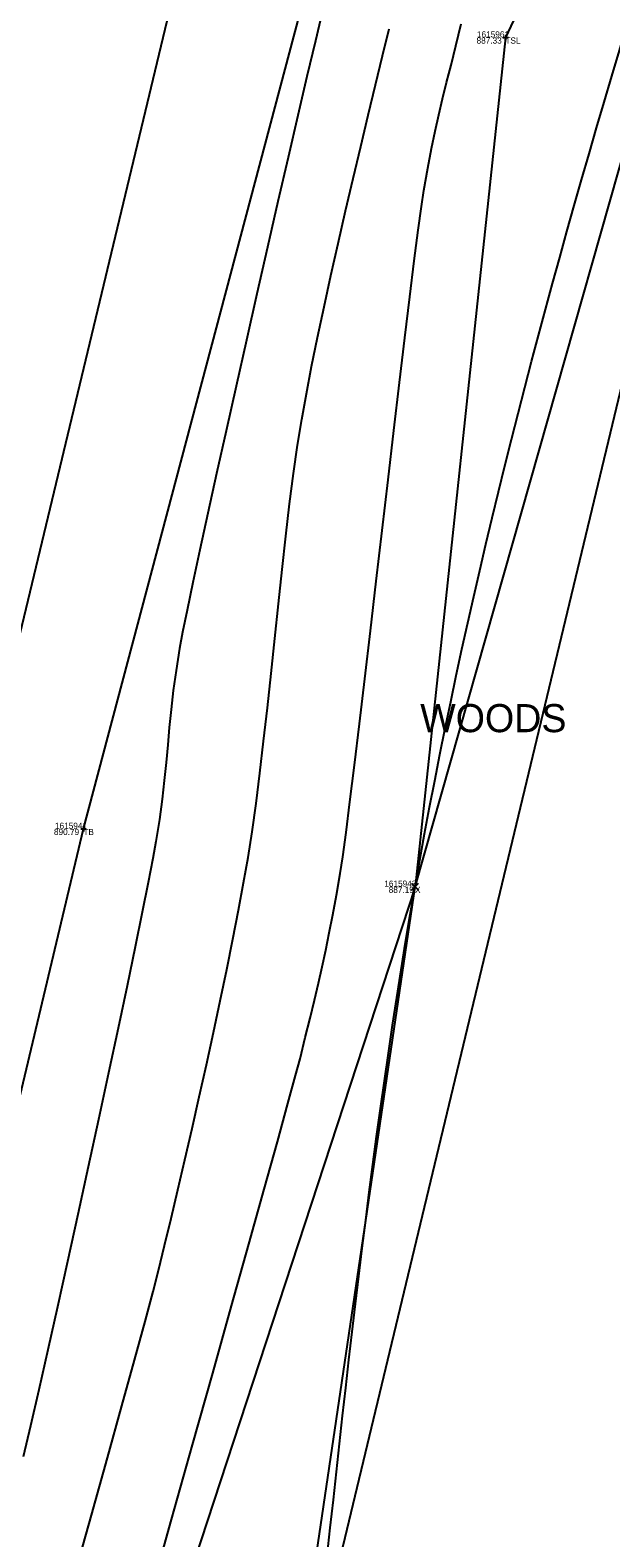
# Model space of a CAD drawing. Extents: x 1957117 to 1971063, y 701601 to 715861.
# Drawn here: x 1963126.8 to 1963159.8, y 705169.7 to 705255.5 of the extents above; entities that cross this region are included whole.
import ezdxf

# ---------------------------------------------------------------- set-up
doc = ezdxf.new("R2010")
doc.units = 0
for name, color, linetype in [('AP_X_Lights', 7, 'Continuous'), ('DT_X_Break_Line', 7, 'Continuous'), ('DT_X_Contour_Major', 7, 'Continuous'), ('DT_X_Contour_Minor', 7, 'Continuous'), ('DT_X_TIN_Hull', 7, 'Continuous'), ('GE_X_CL_20', 7, 'Continuous'), ('HY_X_Water_Edge', 7, 'Continuous'), ('PV_P_Drive', 7, 'Continuous'), ('PV_P_Shoulder', 7, 'Continuous'), ('RS_Raster1', 7, 'Continuous'), ('RW_X_Esmt_RR', 7, 'Continuous'), ('SC_Scratch1', 7, 'Continuous'), ('SC_Shading5', 7, 'Continuous'), ('VG_X_Text', 7, 'Continuous')]:
    doc.layers.add(name, color=color, linetype=linetype)

msp = doc.modelspace()

# ---------------------------------------------------------------- linework, layer by layer
at = {"layer": 'AP_X_Lights'}
for p, q in [((1963148.491, 705206.545), (1963148.879, 705206.935)), ((1963148.491, 705206.935), (1963148.879, 705206.545))]:
    msp.add_line(p, q, dxfattribs=at)
at = {"layer": 'DT_X_Break_Line'}
for points in [[(1963097.69, 705062.728), (1963110.134, 705110.941), (1963118.179, 705161.08), (1963129.819, 705210.034), (1963142.677, 705258.498), (1963154.883, 705308.22), (1963169.696, 705358.61), (1963178.568, 705401.323), (1963191.579, 705451.786), (1963203.047, 705496.926), (1963213.073, 705549.098), (1963225.99, 705592.54), (1963238.509, 705645.64), (1963250.08, 705699.351), (1963260.722, 705745.719)], [(1963274.602, 705735.973), (1963275.289, 705693.429), (1963252.817, 705638.247), (1963242.54, 705592.994), (1963230.124, 705549.475), (1963219.532, 705497.27), (1963210.988, 705447.286), (1963195.628, 705399.31), (1963191.635, 705353.417), (1963175.48, 705301.059), (1963153.825, 705255.066), (1963148.685, 705206.74), (1963116.889, 705109.729), (1963101.597, 705034.688)]]:
    msp.add_lwpolyline(points, dxfattribs=at)
at = {"layer": 'DT_X_Contour_Major'}
msp.add_lwpolyline([(1963143.438, 705256.654), (1963143.014, 705254.873), (1963142.538, 705252.851), (1963142.019, 705250.626), (1963141.465, 705248.237), (1963140.887, 705245.724), (1963140.292, 705243.128), (1963139.69, 705240.486), (1963139.091, 705237.839), (1963138.503, 705235.227), (1963137.935, 705232.688), (1963137.396, 705230.263), (1963136.896, 705227.99), (1963136.444, 705225.91), (1963136.048, 705224.061), (1963135.719, 705222.484), (1963135.464, 705221.218), (1963135.293, 705220.302), (1963135.091, 705219.051), (1963134.933, 705217.902), (1963134.808, 705216.829), (1963134.705, 705215.806), (1963134.614, 705214.809), (1963134.523, 705213.811), (1963134.421, 705212.789), (1963134.299, 705211.715), (1963134.144, 705210.565), (1963133.947, 705209.313), (1963133.77, 705208.337), (1963133.507, 705206.981), (1963133.167, 705205.293), (1963132.762, 705203.319), (1963132.3, 705201.106), (1963131.792, 705198.7), (1963131.248, 705196.148), (1963130.678, 705193.496), (1963130.092, 705190.792), (1963129.5, 705188.082), (1963128.913, 705185.411), (1963128.34, 705182.828), (1963127.792, 705180.379), (1963127.278, 705178.11), (1963126.808, 705176.068), (1963126.393, 705174.299)], dxfattribs=at)
msp.add_lwpolyline([(1963143.438, 705256.654), (1963143.014, 705254.873), (1963142.538, 705252.851), (1963142.019, 705250.626), (1963141.465, 705248.237), (1963140.887, 705245.724), (1963140.292, 705243.128), (1963139.69, 705240.486), (1963139.091, 705237.839), (1963138.503, 705235.227), (1963137.935, 705232.688), (1963137.396, 705230.263), (1963136.896, 705227.99), (1963136.444, 705225.91), (1963136.048, 705224.061), (1963135.719, 705222.484), (1963135.464, 705221.218), (1963135.293, 705220.302), (1963135.091, 705219.051), (1963134.933, 705217.902), (1963134.808, 705216.829), (1963134.705, 705215.806), (1963134.614, 705214.809), (1963134.523, 705213.811), (1963134.421, 705212.789), (1963134.299, 705211.715), (1963134.144, 705210.565), (1963133.947, 705209.313), (1963133.77, 705208.337), (1963133.507, 705206.981), (1963133.167, 705205.293), (1963132.762, 705203.319), (1963132.3, 705201.106), (1963131.792, 705198.7), (1963131.248, 705196.148), (1963130.678, 705193.496), (1963130.092, 705190.792), (1963129.5, 705188.082), (1963128.913, 705185.411), (1963128.34, 705182.828), (1963127.792, 705180.379), (1963127.278, 705178.11), (1963126.808, 705176.068), (1963126.393, 705174.299)], dxfattribs=at)
at = {"layer": 'DT_X_Contour_Minor'}
for points in [[(1963133.609, 705166.375), (1963134.835, 705170.737), (1963136.029, 705174.986), (1963137.173, 705179.057), (1963138.247, 705182.882), (1963139.232, 705186.395), (1963140.108, 705189.53), (1963140.856, 705192.219), (1963141.457, 705194.396), (1963141.892, 705195.993), (1963142.141, 705196.945), (1963142.44, 705198.156), (1963142.712, 705199.259), (1963142.96, 705200.28), (1963143.189, 705201.248), (1963143.403, 705202.191), (1963143.609, 705203.135), (1963143.809, 705204.109), (1963144.009, 705205.14), (1963144.213, 705206.255), (1963144.426, 705207.484), (1963144.57, 705208.436), (1963144.758, 705209.818), (1963144.982, 705211.577), (1963145.239, 705213.658), (1963145.522, 705216.007), (1963145.827, 705218.571), (1963146.147, 705221.295), (1963146.478, 705224.125), (1963146.813, 705227.006), (1963147.149, 705229.886), (1963147.479, 705232.71), (1963147.799, 705235.423), (1963148.101, 705237.972), (1963148.383, 705240.303), (1963148.637, 705242.362), (1963148.859, 705244.094), (1963149.044, 705245.445), (1963149.185, 705246.362), (1963149.412, 705247.631), (1963149.626, 705248.742), (1963149.833, 705249.74), (1963150.04, 705250.668), (1963150.254, 705251.572), (1963150.482, 705252.497), (1963150.73, 705253.486), (1963151.006, 705254.585), (1963151.315, 705255.839)], [(1963133.609, 705166.375), (1963134.835, 705170.737), (1963136.029, 705174.986), (1963137.173, 705179.057), (1963138.247, 705182.882), (1963139.232, 705186.395), (1963140.108, 705189.53), (1963140.856, 705192.219), (1963141.457, 705194.396), (1963141.892, 705195.993), (1963142.141, 705196.945), (1963142.44, 705198.156), (1963142.712, 705199.259), (1963142.96, 705200.28), (1963143.189, 705201.248), (1963143.403, 705202.191), (1963143.609, 705203.135), (1963143.809, 705204.109), (1963144.009, 705205.14), (1963144.213, 705206.255), (1963144.426, 705207.484), (1963144.57, 705208.436), (1963144.758, 705209.818), (1963144.982, 705211.577), (1963145.239, 705213.658), (1963145.522, 705216.007), (1963145.827, 705218.571), (1963146.147, 705221.295), (1963146.478, 705224.125), (1963146.813, 705227.006), (1963147.149, 705229.886), (1963147.479, 705232.71), (1963147.799, 705235.423), (1963148.101, 705237.972), (1963148.383, 705240.303), (1963148.637, 705242.362), (1963148.859, 705244.094), (1963149.044, 705245.445), (1963149.185, 705246.362), (1963149.412, 705247.631), (1963149.626, 705248.742), (1963149.833, 705249.74), (1963150.04, 705250.668), (1963150.254, 705251.572), (1963150.482, 705252.497), (1963150.73, 705253.486), (1963151.006, 705254.585), (1963151.315, 705255.839)], [(1963129.303, 705167.462), (1963130.283, 705170.971), (1963131.192, 705174.235), (1963132.013, 705177.198), (1963132.73, 705179.802), (1963133.326, 705181.991), (1963133.786, 705183.709), (1963134.092, 705184.898), (1963134.44, 705186.321), (1963134.811, 705187.859), (1963135.198, 705189.494), (1963135.597, 705191.205), (1963136.003, 705192.975), (1963136.412, 705194.783), (1963136.819, 705196.612), (1963137.218, 705198.443), (1963137.604, 705200.256), (1963137.974, 705202.033), (1963138.322, 705203.755), (1963138.643, 705205.402), (1963138.933, 705206.956), (1963139.187, 705208.398), (1963139.416, 705209.86), (1963139.64, 705211.468), (1963139.858, 705213.199), (1963140.072, 705215.027), (1963140.284, 705216.929), (1963140.493, 705218.881), (1963140.702, 705220.857), (1963140.911, 705222.833), (1963141.122, 705224.785), (1963141.335, 705226.689), (1963141.552, 705228.52), (1963141.775, 705230.254), (1963142.003, 705231.866), (1963142.239, 705233.332), (1963142.501, 705234.78), (1963142.804, 705236.343), (1963143.142, 705238), (1963143.51, 705239.734), (1963143.902, 705241.523), (1963144.311, 705243.35), (1963144.733, 705245.195), (1963145.162, 705247.039), (1963145.592, 705248.862), (1963146.017, 705250.645), (1963146.432, 705252.37), (1963146.831, 705254.016), (1963147.208, 705255.564)], [(1963129.303, 705167.462), (1963130.283, 705170.971), (1963131.192, 705174.235), (1963132.013, 705177.198), (1963132.73, 705179.802), (1963133.326, 705181.991), (1963133.786, 705183.709), (1963134.092, 705184.898), (1963134.44, 705186.321), (1963134.811, 705187.859), (1963135.198, 705189.494), (1963135.597, 705191.205), (1963136.003, 705192.975), (1963136.412, 705194.783), (1963136.819, 705196.612), (1963137.218, 705198.443), (1963137.604, 705200.256), (1963137.974, 705202.033), (1963138.322, 705203.755), (1963138.643, 705205.402), (1963138.933, 705206.956), (1963139.187, 705208.398), (1963139.416, 705209.86), (1963139.64, 705211.468), (1963139.858, 705213.199), (1963140.072, 705215.027), (1963140.284, 705216.929), (1963140.493, 705218.881), (1963140.702, 705220.857), (1963140.911, 705222.833), (1963141.122, 705224.785), (1963141.335, 705226.689), (1963141.552, 705228.52), (1963141.775, 705230.254), (1963142.003, 705231.866), (1963142.239, 705233.332), (1963142.501, 705234.78), (1963142.804, 705236.343), (1963143.142, 705238), (1963143.51, 705239.734), (1963143.902, 705241.523), (1963144.311, 705243.35), (1963144.733, 705245.195), (1963145.162, 705247.039), (1963145.592, 705248.862), (1963146.017, 705250.645), (1963146.432, 705252.37), (1963146.831, 705254.016), (1963147.208, 705255.564)]]:
    msp.add_lwpolyline(points, dxfattribs=at)
at = {"layer": 'DT_X_TIN_Hull'}
msp.add_lwpolyline([(1963110.114, 705008.741), (1963133.773, 705105.742), (1963148.685, 705206.74), (1963175.48, 705301.059), (1963191.635, 705353.417), (1963195.628, 705399.31), (1963210.988, 705447.286), (1963219.532, 705497.27), (1963230.124, 705549.475), (1963251.052, 705591.159), (1963275.289, 705693.429), (1963292.982, 705784.032), (1963302.841, 705839.645), (1963309.732, 705887.345), (1963335.126, 705936.766)], dxfattribs=at)
at = {"layer": 'GE_X_CL_20'}
msp.add_lwpolyline([(1963418.3, 706437.397), (1962895.621, 704261.062)], dxfattribs=at)
at = {"layer": 'HY_X_Water_Edge'}
msp.add_spline([(1963191.723, 701994.048), (1963062.047, 702441.167), (1962863.491, 703169.356), (1962827.53, 703438.691), (1962823.213, 703537.412), (1962817.962, 703593.874), (1962817.97, 703697.316), (1962828.582, 703804.235), (1962836.461, 703844.734), (1962850.687, 703896.004), (1962867.251, 703938.846), (1962873.848, 703992.355), (1962884.135, 704091.371), (1962891.241, 704140.854), (1962897.382, 704180.529), (1962905.467, 704230.979), (1962943.949, 704328.022), (1962948.537, 704378.842), (1962964.114, 704426.264), (1963004.885, 704570.73), (1963042.054, 704716.522), (1963062.038, 704814.417), (1963072.171, 704860.237), (1963090.023, 704956.798), (1963107.066, 705031.783), (1963133.773, 705105.742), (1963148.685, 705206.74), (1963175.48, 705301.059), (1963191.635, 705353.417), (1963210.988, 705447.286), (1963219.532, 705497.27), (1963230.124, 705549.475), (1963251.052, 705591.159), (1963275.289, 705693.429), (1963292.982, 705784.032), (1963302.841, 705839.645), (1963335.126, 705936.766), (1963359.752, 706046.75), (1963389.133, 706177.299), (1963417.827, 706273.456), (1963475.868, 706451.902), (1963533.782, 706640.53), (1963553.86, 706696.984), (1963580.184, 706715.425), (1963609.172, 706718.73), (1963617.062, 706714.691), (1963619.447, 706694.678), (1963564.282, 706533.07), (1963531.853, 706395.229), (1963434.4, 706006.96), (1963354.09, 705679.186), (1963237.513, 705206.07), (1963167.369, 704892.962), (1963059.145, 704434.176), (1962907.914, 703908.742), (1962877.458, 703703.326), (1962898.357, 703412.121), (1962942.65, 703052.267), (1963048.963, 702674.866), (1963191.468, 702189.666), (1963245.396, 702019.832)], degree=3, dxfattribs=at)
at = {"layer": 'PV_P_Drive'}
for p, q in [((1963153.679, 705255.066), (1963153.971, 705255.066)), ((1963153.825, 705255.212), (1963153.825, 705254.92)), ((1963153.825, 705255.066), (1963153.825, 705255.066)), ((1963129.673, 705210.034), (1963129.965, 705210.034)), ((1963129.819, 705210.18), (1963129.819, 705209.888)), ((1963129.819, 705210.034), (1963129.819, 705210.034))]:
    msp.add_line(p, q, dxfattribs=at)
at = {"layer": 'RW_X_Esmt_RR'}
msp.add_line((1962924.791, 704254.057), (1963447.47, 706430.392), dxfattribs=at)
at = {"layer": 'SC_Shading5'}
for points in [[(1963026.912, 704294.121), (1963138.818, 704737.794), (1963251.679, 705213.963), (1963374.306, 705730.111), (1963454.783, 706045.593), (1963517.244, 706296.713), (1963562.763, 706479.256), (1963580.13, 706553.799), (1963589.678, 706586.994)], [(1963609.915, 706579.703), (1963587.283, 706499.153), (1963552.056, 706354.005), (1963480.911, 706069.234), (1963357.401, 705576.869), (1963272.751, 705226.931), (1963210.247, 704956.481), (1963044.97, 704288.881)]]:
    msp.add_spline(points, degree=3, dxfattribs=at)

# ---------------------------------------------------------------- texts
at = {"layer": 'PV_P_Shoulder'}
for s, p in [('887.33', (1963152.185, 705254.716)), ('890.79', (1963128.144, 705209.684)), ('887.19', (1963147.186, 705206.39))]:
    msp.add_text(s, height=0.35, dxfattribs=at).set_placement(p)
at = {"layer": 'RS_Raster1'}
for s, p in [('1615961', (1963152.207, 705255.066)), ('1615941', (1963128.204, 705210.034)), ('1615943', (1963146.938, 705206.74))]:
    msp.add_text(s, height=0.35, dxfattribs=at).set_placement(p)
at = {"layer": 'SC_Scratch1'}
for s, p in [('TSL', (1963153.825, 705254.716)), ('TB', (1963129.819, 705209.684)), ('X', (1963148.685, 705206.39))]:
    msp.add_text(s, height=0.35, dxfattribs=at).set_placement(p)
at = {"layer": 'VG_X_Text'}
msp.add_text('WOODS', height=1.6, dxfattribs=at).set_placement((1963148.978, 705215.534))

doc.saveas('drawing.dxf')
